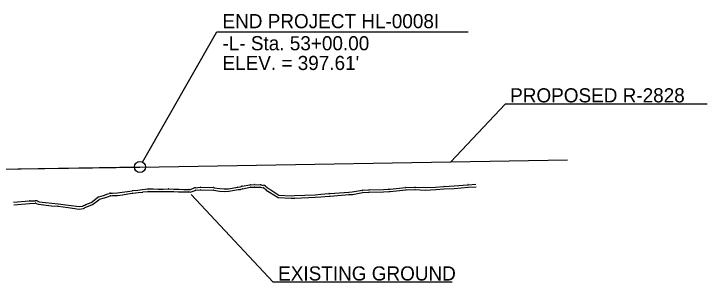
# Model space of a CAD drawing. Extents: x 1625686 to 1640492, y 1161393 to 1175642.
# Drawn here: x 1640149.4 to 1640492.4, y 1175091.8 to 1175224.6 of the extents above; entities that cross this region are included whole.
import ezdxf

# ---------------------------------------------------------------- set-up
doc = ezdxf.new("R2010")
doc.units = 0
for name, color, linetype in [('Exist Vertical Profile Ground Line', 7, 'Continuous'), ('Prop Vertical Profile Grade', 7, 'Continuous'), ('Prop VPI Label', 7, 'Continuous'), ('Scratch_Level_1', 7, 'Continuous'), ('Scratch_Level_3', 7, 'Continuous')]:
    doc.layers.add(name, color=color, linetype=linetype)

msp = doc.modelspace()

# ---------------------------------------------------------------- linework, layer by layer
at = {"layer": 'Exist Vertical Profile Ground Line'}
msp.add_line((1640211.78, 1175148.81), (1640423.28, 1175152.31), dxfattribs=at)
at = {"layer": 'Prop Vertical Profile Grade'}
msp.add_line((1640036.78, 1175146.19), (1640211.78, 1175148.84), dxfattribs=at)
at = {"layer": 'Prop VPI Label'}
for p, q in [((1640213.05, 1175151.28), (1640249.8, 1175215.78)), ((1640249.8, 1175215.78), (1640374.16, 1175215.78)), ((1640392.41, 1175179.99), (1640365.57, 1175151.36)), ((1640492.37, 1175179.99), (1640392.41, 1175179.99)), ((1640277.65, 1175091.83), (1640237.08, 1175135.18)), ((1640366.26, 1175091.83), (1640277.65, 1175091.83))]:
    msp.add_line(p, q, dxfattribs=at)
msp.add_circle((1640211.78, 1175148.84), 2.75, dxfattribs=at)
at = {"layer": 'Scratch_Level_1'}
for p, q in [((1640239.34, 1175138.58), (1640241.54, 1175138.76)), ((1640241.81, 1175138.77), (1640248.18, 1175138.61)), ((1640262.32, 1175139.31), (1640266.17, 1175139.99)), ((1640262.54, 1175138.08), (1640266.39, 1175138.76)), ((1640266.51, 1175140.03), (1640268.28, 1175140.1)), ((1640266.56, 1175138.78), (1640268.33, 1175138.85)), ((1640268.4, 1175138.85), (1640271.21, 1175138.81)), ((1640268.42, 1175140.1), (1640271.23, 1175140.06)), ((1640271.44, 1175138.79), (1640272.73, 1175138.52)), ((1640271.7, 1175140.01), (1640272.98, 1175139.74)), ((1640273.22, 1175138.31), (1640273.73, 1175137.93)), ((1640273.95, 1175139.31), (1640274.47, 1175138.94)), ((1640343.37, 1175138.7), (1640347.73, 1175138.91)), ((1640374.11, 1175140.07), (1640377.99, 1175140.25)), ((1640374.17, 1175138.82), (1640378.05, 1175139)), ((1640195.88, 1175135.46), (1640196.59, 1175135.7)), ((1640205.65, 1175136.72), (1640207.99, 1175137.09)), ((1640205.85, 1175135.48), (1640208.18, 1175135.86)), ((1640213.14, 1175137.69), (1640215.64, 1175137.93)), ((1640213.26, 1175136.45), (1640215.76, 1175136.69)), ((1640215.89, 1175136.69), (1640218.39, 1175136.68)), ((1640215.9, 1175137.94), (1640218.4, 1175137.93)), ((1640225.97, 1175136.74), (1640228.5, 1175136.65)), ((1640226.02, 1175137.99), (1640228.54, 1175137.9)), ((1640239.44, 1175137.34), (1640241.64, 1175137.52)), ((1640241.78, 1175137.52), (1640248.15, 1175137.36)), ((1640321.97, 1175137.4), (1640325, 1175137.59)), ((1640322.05, 1175136.15), (1640325.08, 1175136.34)), ((1640343.42, 1175137.45), (1640347.79, 1175137.66)), ((1640149.32, 1175131.33), (1640157.05, 1175132.05)), ((1640157.2, 1175132.06), (1640159.98, 1175132.14)), ((1640196.29, 1175134.28), (1640197, 1175134.52)), ((1640149.44, 1175130.09), (1640157.16, 1175130.8)), ((1640157.24, 1175130.81), (1640160.02, 1175130.89)), ((1640171.27, 1175129.35), (1640176.26, 1175128.74)), ((1640171.42, 1175130.59), (1640176.41, 1175129.98)), ((1640184.13, 1175129.84), (1640185.02, 1175130.22)), ((1640184.61, 1175128.69), (1640185.5, 1175129.07))]:
    msp.add_line(p, q, dxfattribs=at)
for points in [[(1640236.22, 1175137.74), (1640236.73, 1175137.7), (1640238.66, 1175138.43)], [(1640248.47, 1175138.58), (1640251.36, 1175138.17), (1640253.45, 1175137.97), (1640255.55, 1175138.06), (1640260.12, 1175138.86)], [(1640260.28, 1175138.89), (1640261.3, 1175139), (1640261.39, 1175139.01), (1640261.91, 1175139.2)], [(1640274.75, 1175138.7), (1640275.05, 1175138.4), (1640276.49, 1175137.45), (1640280.54, 1175134.94), (1640286.66, 1175134.58), (1640288.31, 1175134.64), (1640298.48, 1175135.12), (1640301.25, 1175135.3), (1640305.25, 1175135.65)], [(1640334.84, 1175137.87), (1640335.5, 1175137.9), (1640343.23, 1175138.69)], [(1640347.98, 1175138.91), (1640352.84, 1175138.65), (1640358.05, 1175138.9), (1640362.18, 1175139.23)], [(1640362.27, 1175139.23), (1640367.2, 1175139.45), (1640374, 1175140.07)], [(1640362.32, 1175137.98), (1640367.28, 1175138.21), (1640374.11, 1175138.82)], [(1640191.49, 1175134.03), (1640193.81, 1175134.74), (1640195.88, 1175135.46)], [(1640197.3, 1175135.84), (1640198.25, 1175135.88), (1640200.66, 1175135.98), (1640203.02, 1175136.29), (1640205.65, 1175136.72)], [(1640197.35, 1175134.59), (1640198.3, 1175134.63), (1640200.77, 1175134.73), (1640203.2, 1175135.06), (1640205.85, 1175135.48)], [(1640208.1, 1175137.11), (1640210.71, 1175137.4), (1640213.09, 1175137.68)], [(1640208.24, 1175135.87), (1640210.85, 1175136.16), (1640213.23, 1175136.44)], [(1640218.39, 1175136.68), (1640220.89, 1175136.66), (1640221.93, 1175136.66), (1640223.36, 1175136.66), (1640225.89, 1175136.74)], [(1640218.4, 1175137.93), (1640220.89, 1175137.91), (1640221.94, 1175137.91), (1640223.35, 1175137.91), (1640225.85, 1175137.99)], [(1640228.52, 1175136.65), (1640230.93, 1175136.52), (1640233.51, 1175136.46), (1640236.05, 1175136.49)], [(1640228.58, 1175137.9), (1640230.98, 1175137.77), (1640233.52, 1175137.71), (1640236.03, 1175137.74)], [(1640236.14, 1175136.49), (1640236.91, 1175136.44), (1640237.14, 1175136.52), (1640239.1, 1175137.26)], [(1640248.29, 1175137.34), (1640251.21, 1175136.93), (1640253.42, 1175136.71), (1640255.69, 1175136.81), (1640260.34, 1175137.63)], [(1640260.42, 1175137.64), (1640261.47, 1175137.76), (1640261.72, 1175137.8), (1640262.33, 1175138.02)], [(1640273.87, 1175137.81), (1640274.26, 1175137.42), (1640275.82, 1175136.4), (1640280.15, 1175133.71), (1640286.64, 1175133.33), (1640288.36, 1175133.39), (1640298.55, 1175133.87), (1640301.35, 1175134.05), (1640305.36, 1175134.41)], [(1640305.37, 1175135.66), (1640305.82, 1175135.68), (1640315.08, 1175136.43)], [(1640305.42, 1175134.41), (1640305.89, 1175134.43), (1640315.18, 1175135.18)], [(1640315.2, 1175136.44), (1640316.76, 1175136.48), (1640321.68, 1175137.37)], [(1640315.24, 1175135.19), (1640316.89, 1175135.24), (1640321.9, 1175136.14)], [(1640325.11, 1175137.59), (1640332.29, 1175137.71), (1640334.81, 1175137.87)], [(1640325.13, 1175136.34), (1640332.34, 1175136.46), (1640334.89, 1175136.62)], [(1640334.91, 1175136.62), (1640335.59, 1175136.65), (1640343.36, 1175137.45)], [(1640347.92, 1175137.66), (1640352.83, 1175137.4), (1640358.13, 1175137.65), (1640362.28, 1175137.98)], [(1640160.91, 1175131.99), (1640161.91, 1175131.63), (1640168.23, 1175130.9), (1640171.36, 1175130.6)], [(1640185.07, 1175130.24), (1640187.74, 1175131.3), (1640190.67, 1175133.61)], [(1640185.53, 1175129.08), (1640188.37, 1175130.2), (1640191.45, 1175132.63)], [(1640191.85, 1175132.84), (1640194.2, 1175133.56), (1640196.29, 1175134.28)], [(1640160.49, 1175130.82), (1640161.62, 1175130.41), (1640168.1, 1175129.66), (1640171.24, 1175129.35)], [(1640176.29, 1175128.74), (1640181.73, 1175127.94), (1640183.83, 1175128.31), (1640184.55, 1175128.66)], [(1640176.47, 1175129.97), (1640181.71, 1175129.21), (1640183.44, 1175129.51), (1640184.01, 1175129.79)]]:
    msp.add_lwpolyline(points, dxfattribs=at)
for centre, radius, start, end in [((1640239.54, 1175136.09), 2.5, 94.6742, 110.6376), ((1640241.74, 1175136.27), 2.5, 88.5173, 94.6742), ((1640248.12, 1175136.11), 2.5, 81.9622, 88.5173), ((1640260.55, 1175136.4), 2.5, 96.1835, 99.9774), ((1640262.76, 1175136.85), 2.5, 100.0506, 109.9245), ((1640266.61, 1175137.53), 2.5, 92.2901, 100.0506), ((1640266.61, 1175137.53), 1.25, 92.2901, 100.0506), ((1640268.38, 1175137.6), 2.5, 89.1756, 92.2901), ((1640268.38, 1175137.6), 1.25, 89.1756, 92.2901), ((1640271.19, 1175137.56), 1.25, 78.3394, 89.1756), ((1640271.19, 1175137.56), 2.5, 78.3394, 89.1756), ((1640272.48, 1175137.3), 1.25, 53.8707, 78.3394), ((1640272.48, 1175137.3), 2.5, 53.8707, 78.3394), ((1640273, 1175136.92), 2.5, 45.5192, 53.8707), ((1640343.48, 1175136.2), 2.5, 92.7148, 95.8426), ((1640347.85, 1175136.41), 2.5, 86.9318, 92.7148), ((1640362.38, 1175136.74), 2.5, 92.5694, 94.609), ((1640374.23, 1175137.58), 2.5, 92.5786, 95.1312), ((1640374.23, 1175137.58), 1.25, 92.5786, 95.1312), ((1640196.7, 1175133.1), 2.5, 108.9292, 109.0564), ((1640197.4, 1175133.34), 2.5, 92.4237, 108.9292), ((1640206.05, 1175134.25), 2.5, 99.1137, 99.1208), ((1640206.05, 1175134.25), 1.25, 99.1137, 99.1208), ((1640208.38, 1175134.62), 2.5, 96.433, 99.1137), ((1640208.38, 1175134.62), 1.25, 96.433, 99.1137), ((1640213.38, 1175135.2), 2.5, 95.4963, 96.752), ((1640213.38, 1175135.2), 1.25, 95.4963, 96.752), ((1640215.88, 1175135.44), 2.5, 89.6932, 95.4963), ((1640215.88, 1175135.44), 1.25, 89.6932, 95.4963), ((1640218.38, 1175135.43), 1.25, 89.6777, 89.6932), ((1640218.38, 1175135.43), 2.5, 89.6777, 89.6932), ((1640225.92, 1175135.49), 2.5, 87.9222, 91.8014), ((1640225.92, 1175135.49), 1.25, 87.9222, 91.8014), ((1640228.45, 1175135.4), 1.25, 87.0492, 87.9222), ((1640228.45, 1175135.4), 2.5, 87.0492, 87.9222), ((1640236.06, 1175135.24), 2.5, 86.342, 90.6303), ((1640236.06, 1175135.24), 1.25, 86.342, 90.6303), ((1640239.54, 1175136.09), 1.25, 94.6742, 110.6376), ((1640241.74, 1175136.27), 1.25, 88.5173, 94.6742), ((1640248.12, 1175136.11), 1.25, 81.9622, 88.5173), ((1640260.55, 1175136.4), 1.25, 96.1835, 99.9774), ((1640262.76, 1175136.85), 1.25, 100.0506, 109.9245), ((1640273, 1175136.92), 1.25, 45.5192, 53.8707), ((1640305.47, 1175133.16), 2.5, 92.1129, 95.0088), ((1640315.28, 1175133.94), 2.5, 91.7402, 94.6531), ((1640315.28, 1175133.94), 1.25, 91.7402, 94.6531), ((1640322.12, 1175134.91), 2.5, 93.5573, 100.1635), ((1640322.12, 1175134.91), 1.25, 93.5573, 100.1635), ((1640325.15, 1175135.09), 2.5, 90.9471, 93.5573), ((1640325.15, 1175135.09), 1.25, 90.9471, 93.5573), ((1640334.97, 1175135.37), 2.5, 92.7689, 93.505), ((1640334.97, 1175135.37), 1.25, 92.7689, 93.505), ((1640343.48, 1175136.2), 1.25, 92.7148, 95.8426), ((1640347.85, 1175136.41), 1.25, 86.9318, 92.7148), ((1640362.38, 1175136.74), 1.25, 92.5694, 94.609), ((1640157.28, 1175129.56), 2.5, 91.8054, 95.2937), ((1640160.06, 1175129.64), 2.5, 70.0648, 91.8054), ((1640192.22, 1175131.64), 2.5, 107.0188, 128.188), ((1640192.22, 1175131.64), 1.25, 107.0188, 128.188), ((1640196.7, 1175133.1), 1.25, 108.9292, 109.0564), ((1640197.4, 1175133.34), 1.25, 92.4237, 108.9292), ((1640305.47, 1175133.16), 1.25, 92.1129, 95.0088), ((1640149.55, 1175128.84), 1.25, 95.2937, 99.3614), ((1640157.28, 1175129.56), 1.25, 91.8054, 95.2937), ((1640160.06, 1175129.64), 1.25, 70.0648, 91.8054), ((1640171.12, 1175128.11), 1.25, 83.034, 84.3731), ((1640171.12, 1175128.11), 2.5, 83.034, 84.3731), ((1640176.11, 1175127.5), 1.25, 81.7193, 83.034), ((1640176.11, 1175127.5), 2.5, 81.7193, 83.034), ((1640185.1, 1175127.54), 2.5, 112.9332, 115.9662), ((1640185.1, 1175127.54), 1.25, 112.9332, 115.9662), ((1640185.99, 1175127.92), 2.5, 111.6055, 112.9332), ((1640185.99, 1175127.92), 1.25, 111.6055, 112.9332)]:
    msp.add_arc(centre, radius, start, end, dxfattribs=at)
at = {"layer": 'Scratch_Level_3'}
msp.add_line((1640036.78, 1175146.19), (1640211.78, 1175148.81), dxfattribs=at)

# ---------------------------------------------------------------- texts
at = {"layer": 'Prop VPI Label'}
for s, p in [('END PROJECT HL-0008I', (1640252.64, 1175217.51)), ('-L- Sta. 53+00.00', (1640252.64, 1175206.57)), ("ELEV. = 397.61'", (1640252.64, 1175196.82)), ('PROPOSED R-2828', (1640394.93, 1175180.79)), ('EXISTING GROUND', (1640280.17, 1175092.63))]:
    msp.add_text(s, height=7, dxfattribs=at).set_placement(p)

doc.saveas('drawing.dxf')
